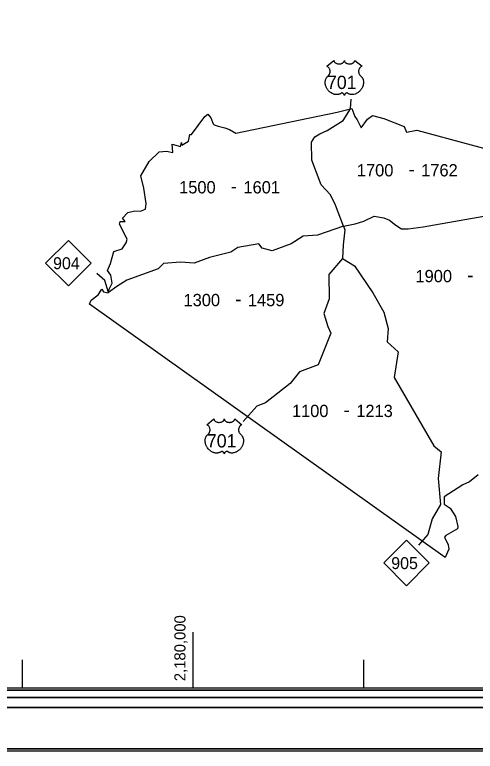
# Model space of a CAD drawing. Extents: x 5197761 to 5514561, y 1890130 to 2080942.
# Drawn here: x 5400329 to 5427322, y 1890130 to 1933323 of the extents above; entities that cross this region are included whole.
import ezdxf

# ---------------------------------------------------------------- set-up
doc = ezdxf.new("R2010")
doc.units = 0
for name, color, linetype in [('Exist Road Primary NC Shield CELL', 7, 'Continuous'), ('Exist Road Primary NC Shield Number Label', 7, 'Continuous'), ('Exist Road Primary US Shield CELL', 7, 'Continuous'), ('Exist Road Primary US Shield Number Label', 7, 'Continuous'), ('Map Preparation Base KeyMap Boundary Shape', 7, 'Continuous'), ('Map Preparation Base KeyMap Note Label', 7, 'Continuous'), ('Map Preparation Base StatePlane Tick Label', 7, 'Continuous'), ('Map Preparation Base StatePlane Tick Mark', 7, 'Continuous'), ('Map Preparation Border Antique Large Shape', 7, 'Continuous'), ('Map Preparation Border Antique Small Shape', 7, 'Continuous'), ('Map Preparation Border Black Inside Shape', 7, 'Continuous'), ('Map Preparation Border Black Middle Shape', 7, 'Continuous'), ('Map Preparation Border Black Outside Shape', 7, 'Continuous')]:
    doc.layers.add(name, color=color, linetype=linetype)

msp = doc.modelspace()

# ---------------------------------------------------------------- linework, layer by layer
at = {"layer": 'Exist Road Primary NC Shield CELL'}
for points in [[(5402139, 1918759), (5403471, 1920091), (5404803, 1918759), (5403471, 1917427)], [(5421960, 1901173), (5423292, 1902505), (5424624, 1901173), (5423292, 1899841)]]:
    msp.add_lwpolyline(points, close=True, dxfattribs=at)
at = {"layer": 'Exist Road Primary US Shield CELL'}
for points in [[(5419042, 1930642), (5419043, 1930625), (5419047, 1930604), (5419050, 1930593), (5419060, 1930572), (5419076, 1930548), (5419099, 1930524), (5419124, 1930503), (5419141, 1930492), (5419170, 1930477), (5419203, 1930463), (5419240, 1930452), (5419277, 1930445), (5419318, 1930440), (5419358, 1930440), (5419402, 1930443), (5419450, 1930452), (5419473, 1930458), (5419498, 1930466), (5419521, 1930476), (5419546, 1930490), (5419566, 1930503), (5419582, 1930514), (5419605, 1930536), (5419623, 1930558), (5419630, 1930571), (5419637, 1930583), (5419646, 1930608), (5419648, 1930620), (5419650, 1930643), (5419652, 1930623), (5419654, 1930611), (5419657, 1930599), (5419662, 1930586), (5419671, 1930568), (5419681, 1930553), (5419700, 1930531), (5419712, 1930520), (5419722, 1930511), (5419751, 1930491), (5419785, 1930474), (5419802, 1930467), (5419819, 1930461), (5419840, 1930454), (5419863, 1930449), (5419885, 1930445), (5419907, 1930442), (5419930, 1930440), (5419949, 1930440), (5419972, 1930440), (5419994, 1930441), (5420016, 1930444), (5420040, 1930448), (5420059, 1930452), (5420085, 1930459), (5420108, 1930467), (5420128, 1930476), (5420154, 1930490), (5420176, 1930503), (5420191, 1930515), (5420210, 1930533), (5420227, 1930553), (5420238, 1930568), (5420245, 1930583), (5420252, 1930599), (5420256, 1930616), (5420258, 1930631), (5420258, 1930644), (5420684, 1930305), (5420673, 1930301), (5420650, 1930290), (5420632, 1930279), (5420603, 1930258), (5420590, 1930247), (5420578, 1930235), (5420566, 1930223), (5420556, 1930211), (5420544, 1930194), (5420533, 1930177), (5420522, 1930158), (5420514, 1930142), (5420501, 1930107), (5420495, 1930086), (5420491, 1930068), (5420486, 1930030), (5420484, 1930012), (5420484, 1929994), (5420485, 1929975), (5420487, 1929957), (5420490, 1929938), (5420493, 1929921), (5420499, 1929901), (5420506, 1929877), (5420515, 1929855), (5420535, 1929818), (5420560, 1929780), (5420578, 1929759), (5420595, 1929741), (5420622, 1929719), (5420636, 1929706), (5420652, 1929690), (5420679, 1929659), (5420689, 1929644), (5420700, 1929628), (5420710, 1929611), (5420720, 1929593), (5420728, 1929577), (5420743, 1929541), (5420754, 1929505), (5420759, 1929487), (5420767, 1929445), (5420770, 1929424), (5420774, 1929384), (5420774, 1929335), (5420770, 1929288), (5420761, 1929233), (5420754, 1929201), (5420743, 1929163), (5420732, 1929130), (5420712, 1929081), (5420695, 1929046), (5420673, 1929005), (5420658, 1928980), (5420640, 1928953), (5420617, 1928923), (5420591, 1928890), (5420560, 1928856), (5420535, 1928830), (5420501, 1928801), (5420481, 1928784), (5420453, 1928763), (5420414, 1928736), (5420375, 1928714), (5420342, 1928697), (5420313, 1928685), (5420275, 1928670), (5420212, 1928653), (5420190, 1928648), (5420162, 1928644), (5420137, 1928642), (5420113, 1928640), (5420079, 1928640), (5420046, 1928643), (5420015, 1928647), (5419983, 1928654), (5419949, 1928664), (5419918, 1928676), (5419887, 1928692), (5419835, 1928725), (5419819, 1928733), (5419811, 1928735), (5419791, 1928736), (5419771, 1928732), (5419752, 1928724), (5419740, 1928718), (5419724, 1928708), (5419712, 1928698), (5419698, 1928684), (5419688, 1928673), (5419680, 1928664), (5419665, 1928640), (5419660, 1928629), (5419654, 1928615), (5419650, 1928594), (5419643, 1928620), (5419635, 1928638), (5419626, 1928653), (5419617, 1928666), (5419602, 1928683), (5419589, 1928696), (5419572, 1928709), (5419555, 1928720), (5419542, 1928727), (5419529, 1928731), (5419514, 1928735), (5419501, 1928736), (5419491, 1928736), (5419477, 1928733), (5419458, 1928719), (5419439, 1928706), (5419420, 1928694), (5419396, 1928681), (5419379, 1928673), (5419358, 1928665), (5419334, 1928657), (5419308, 1928651), (5419281, 1928645), (5419257, 1928642), (5419232, 1928639), (5419209, 1928638), (5419185, 1928639), (5419163, 1928641), (5419137, 1928643), (5419105, 1928648), (5419078, 1928654), (5419050, 1928661), (5419021, 1928670), (5418990, 1928682), (5418952, 1928699), (5418925, 1928713), (5418883, 1928737), (5418833, 1928771), (5418795, 1928802), (5418768, 1928827), (5418727, 1928868), (5418704, 1928895), (5418666, 1928943), (5418643, 1928978), (5418627, 1929003), (5418604, 1929045), (5418592, 1929071), (5418576, 1929108), (5418563, 1929143), (5418553, 1929175), (5418547, 1929196), (5418539, 1929233), (5418534, 1929258), (5418529, 1929294), (5418527, 1929331), (5418526, 1929366), (5418527, 1929394), (5418530, 1929428), (5418536, 1929463), (5418543, 1929494), (5418549, 1929515), (5418558, 1929542), (5418570, 1929571), (5418584, 1929600), (5418597, 1929623), (5418614, 1929648), (5418631, 1929669), (5418653, 1929693), (5418675, 1929715), (5418696, 1929731), (5418720, 1929756), (5418733, 1929770), (5418749, 1929790), (5418761, 1929809), (5418771, 1929826), (5418784, 1929851), (5418792, 1929870), (5418801, 1929898), (5418806, 1929918), (5418811, 1929944), (5418815, 1929969), (5418816, 1929999), (5418815, 1930024), (5418812, 1930053), (5418806, 1930082), (5418800, 1930106), (5418789, 1930134), (5418779, 1930155), (5418763, 1930183), (5418745, 1930209), (5418726, 1930230), (5418707, 1930249), (5418689, 1930263), (5418672, 1930275), (5418651, 1930288), (5418630, 1930298), (5418617, 1930304)], [(5412004, 1909621), (5412005, 1909603), (5412009, 1909582), (5412012, 1909571), (5412022, 1909551), (5412038, 1909526), (5412061, 1909503), (5412086, 1909482), (5412103, 1909471), (5412132, 1909455), (5412165, 1909441), (5412202, 1909431), (5412239, 1909423), (5412280, 1909419), (5412320, 1909418), (5412364, 1909421), (5412412, 1909431), (5412435, 1909436), (5412460, 1909445), (5412483, 1909454), (5412508, 1909468), (5412528, 1909481), (5412544, 1909493), (5412567, 1909514), (5412585, 1909537), (5412592, 1909549), (5412599, 1909561), (5412608, 1909587), (5412610, 1909598), (5412612, 1909622), (5412614, 1909602), (5412616, 1909590), (5412619, 1909577), (5412624, 1909565), (5412633, 1909547), (5412643, 1909531), (5412662, 1909509), (5412674, 1909498), (5412684, 1909489), (5412713, 1909469), (5412747, 1909452), (5412764, 1909445), (5412781, 1909439), (5412802, 1909433), (5412825, 1909427), (5412847, 1909423), (5412869, 1909420), (5412892, 1909418), (5412911, 1909418), (5412934, 1909418), (5412956, 1909419), (5412978, 1909422), (5413002, 1909426), (5413021, 1909430), (5413047, 1909437), (5413070, 1909445), (5413090, 1909454), (5413116, 1909468), (5413138, 1909481), (5413153, 1909494), (5413172, 1909511), (5413189, 1909531), (5413200, 1909546), (5413207, 1909561), (5413214, 1909577), (5413218, 1909595), (5413220, 1909609), (5413220, 1909622), (5413646, 1909283), (5413636, 1909280), (5413612, 1909268), (5413594, 1909257), (5413565, 1909237), (5413552, 1909226), (5413540, 1909214), (5413528, 1909201), (5413518, 1909189), (5413506, 1909172), (5413495, 1909155), (5413484, 1909136), (5413476, 1909120), (5413463, 1909086), (5413457, 1909064), (5413453, 1909046), (5413448, 1909008), (5413446, 1908990), (5413446, 1908972), (5413447, 1908953), (5413449, 1908935), (5413452, 1908916), (5413455, 1908900), (5413461, 1908879), (5413468, 1908856), (5413477, 1908833), (5413497, 1908796), (5413522, 1908758), (5413540, 1908737), (5413557, 1908719), (5413584, 1908697), (5413598, 1908684), (5413614, 1908668), (5413641, 1908637), (5413651, 1908623), (5413662, 1908606), (5413672, 1908590), (5413682, 1908571), (5413690, 1908556), (5413705, 1908519), (5413716, 1908484), (5413721, 1908465), (5413729, 1908423), (5413732, 1908403), (5413736, 1908362), (5413736, 1908313), (5413732, 1908266), (5413723, 1908212), (5413716, 1908179), (5413705, 1908141), (5413694, 1908108), (5413674, 1908060), (5413657, 1908025), (5413635, 1907983), (5413620, 1907958), (5413602, 1907932), (5413579, 1907901), (5413553, 1907869), (5413522, 1907834), (5413497, 1907809), (5413463, 1907779), (5413443, 1907763), (5413415, 1907741), (5413376, 1907715), (5413337, 1907692), (5413304, 1907676), (5413275, 1907663), (5413237, 1907649), (5413174, 1907631), (5413152, 1907627), (5413124, 1907623), (5413099, 1907620), (5413075, 1907619), (5413041, 1907619), (5413008, 1907621), (5412977, 1907626), (5412945, 1907632), (5412911, 1907642), (5412880, 1907655), (5412849, 1907670), (5412797, 1907703), (5412781, 1907711), (5412773, 1907713), (5412753, 1907714), (5412733, 1907710), (5412714, 1907703), (5412702, 1907696), (5412686, 1907686), (5412674, 1907676), (5412660, 1907663), (5412650, 1907651), (5412642, 1907642), (5412627, 1907619), (5412622, 1907608), (5412616, 1907593), (5412612, 1907572), (5412605, 1907599), (5412597, 1907616), (5412588, 1907631), (5412579, 1907645), (5412564, 1907662), (5412551, 1907675), (5412534, 1907688), (5412517, 1907698), (5412504, 1907705), (5412491, 1907710), (5412476, 1907714), (5412463, 1907715), (5412453, 1907714), (5412439, 1907711), (5412420, 1907697), (5412401, 1907685), (5412382, 1907672), (5412358, 1907660), (5412341, 1907652), (5412320, 1907644), (5412296, 1907636), (5412270, 1907629), (5412243, 1907624), (5412219, 1907620), (5412194, 1907618), (5412171, 1907617), (5412147, 1907617), (5412125, 1907619), (5412099, 1907621), (5412067, 1907626), (5412040, 1907632), (5412012, 1907639), (5411983, 1907649), (5411952, 1907660), (5411914, 1907677), (5411887, 1907691), (5411845, 1907715), (5411795, 1907750), (5411757, 1907780), (5411730, 1907805), (5411689, 1907846), (5411666, 1907873), (5411628, 1907921), (5411605, 1907956), (5411589, 1907982), (5411566, 1908023), (5411554, 1908049), (5411538, 1908087), (5411525, 1908121), (5411515, 1908154), (5411509, 1908175), (5411501, 1908211), (5411496, 1908237), (5411491, 1908272), (5411489, 1908310), (5411488, 1908344), (5411489, 1908373), (5411492, 1908406), (5411498, 1908442), (5411505, 1908472), (5411511, 1908494), (5411520, 1908520), (5411532, 1908550), (5411546, 1908578), (5411559, 1908601), (5411576, 1908626), (5411593, 1908648), (5411615, 1908671), (5411637, 1908693), (5411658, 1908710), (5411682, 1908734), (5411695, 1908749), (5411711, 1908769), (5411723, 1908788), (5411733, 1908805), (5411746, 1908829), (5411754, 1908848), (5411763, 1908877), (5411768, 1908897), (5411773, 1908923), (5411777, 1908947), (5411778, 1908977), (5411777, 1909002), (5411774, 1909032), (5411768, 1909060), (5411762, 1909085), (5411751, 1909113), (5411741, 1909133), (5411725, 1909161), (5411707, 1909187), (5411688, 1909208), (5411669, 1909227), (5411651, 1909241), (5411634, 1909253), (5411613, 1909266), (5411592, 1909277), (5411579, 1909282)]]:
    msp.add_lwpolyline(points, close=True, dxfattribs=at)
at = {"layer": 'Map Preparation Base KeyMap Boundary Shape'}
for points in [[(5419606, 1920931), (5419136, 1922152), (5418831, 1922764), (5418290, 1923353), (5417748, 1924788), (5417725, 1925848), (5417913, 1926154), (5418219, 1926342), (5418642, 1926530), (5419583, 1927119), (5420007, 1927801), (5420054, 1928366)], [(5404712, 1916341), (5404815, 1916576), (5405212, 1916906), (5405440, 1917228), (5405541, 1917067), (5405809, 1917013), (5405870, 1917221), (5406037, 1917577), (5405957, 1918054), (5405776, 1918316), (5405943, 1918732), (5406131, 1919444), (5406628, 1919598), (5406856, 1919940), (5406910, 1920162), (5406460, 1921042), (5406514, 1921196), (5406796, 1921203), (5406655, 1921391), (5406950, 1921720), (5407359, 1921814), (5407702, 1921807), (5407997, 1921921), (5408030, 1922250), (5407903, 1923150), (5407729, 1923882), (5408218, 1924714), (5408802, 1925278), (5409218, 1925319), (5409601, 1925245), (5409554, 1925742), (5410050, 1925594), (5410111, 1925836), (5410118, 1925674), (5410520, 1925909), (5410587, 1926306), (5410688, 1926292), (5411480, 1927353), (5411641, 1927487), (5411829, 1927279), (5411963, 1926923), (5412023, 1926876), (5412258, 1926782), (5412641, 1926695), (5412916, 1926594), (5413285, 1926373), (5419231, 1927608), (5420090, 1927823), (5420264, 1927353), (5420398, 1927152), (5420627, 1926682), (5421002, 1927192), (5421298, 1927420), (5421969, 1927246), (5423163, 1926762), (5423298, 1926440), (5423902, 1926547), (5430263, 1924842)], [(5419606, 1920931), (5420289, 1921069), (5420783, 1921211), (5421395, 1921517), (5421960, 1921422), (5422289, 1921281), (5422665, 1920975), (5422995, 1920763), (5423395, 1920763), (5424265, 1920881), (5428147, 1921564), (5428782, 1921728), (5429841, 1921893), (5432488, 1922331)], [(5419603, 1920920), (5418071, 1920395), (5417229, 1920344), (5416540, 1919884), (5415418, 1919476), (5414831, 1919629), (5414627, 1919884), (5413403, 1919680), (5412995, 1919400), (5411745, 1919093), (5410853, 1918762), (5410037, 1918813), (5409042, 1918736), (5408736, 1918430), (5406899, 1917766), (5406313, 1917384), (5405824, 1917043), (5405609, 1917735), (5405132, 1918150)], [(5419603, 1920920), (5419686, 1920713), (5419575, 1919822), (5419534, 1919028)], [(5419534, 1919028), (5418734, 1918098), (5418759, 1916669), (5418453, 1915801), (5418683, 1915036), (5418861, 1914653), (5418122, 1912790), (5417025, 1912382), (5416464, 1911693), (5415035, 1910570), (5414525, 1910366), (5413709, 1909473)], [(5419534, 1919028), (5420238, 1918593), (5421312, 1917020), (5421970, 1915884), (5422209, 1914926), (5422149, 1914148), (5422807, 1913550), (5422568, 1912054), (5424900, 1908046), (5425318, 1907687), (5425139, 1906131), (5425286, 1904606), (5424789, 1903753), (5424548, 1902844), (5423994, 1902219)], [(5427485, 1906337), (5426975, 1905934), (5426599, 1905746), (5425499, 1905048), (5425499, 1904618), (5425848, 1904377), (5426170, 1903893), (5426304, 1903302), (5426277, 1903168), (5425606, 1902792), (5425526, 1902685), (5425740, 1902228), (5425781, 1901988), (5425553, 1901493), (5404712, 1916341)]]:
    msp.add_lwpolyline(points, dxfattribs=at)
at = {"layer": 'Map Preparation Base StatePlane Tick Mark'}
for p, q in [((5410787, 1893858), (5410787, 1897109)), ((5400787, 1893858), (5400787, 1895484)), ((5420787, 1893858), (5420787, 1895484))]:
    msp.add_line(p, q, dxfattribs=at)
at = {"layer": 'Map Preparation Border Antique Large Shape'}
msp.add_lwpolyline([(5197907, 2074783), (5207205, 2074783), (5207205, 1892697), (5512539, 1892697), (5512539, 2072359), (5207205, 2072359), (5207205, 2074783), (5514414, 2074783), (5514414, 1890276), (5197907, 1890276)], close=True, dxfattribs=at)
at = {"layer": 'Map Preparation Border Antique Small Shape'}
msp.add_lwpolyline([(5207791, 2071720), (5208220, 2071720), (5208220, 1893712), (5511524, 1893712), (5511524, 2071291), (5208220, 2071291), (5208220, 2071720), (5207791, 2071720), (5511953, 2071720), (5511953, 1893283), (5208220, 1893283), (5207791, 1893283)], close=True, dxfattribs=at)
at = {"layer": 'Map Preparation Border Black Inside Shape'}
msp.add_lwpolyline([(5208220, 2071291), (5511524, 2071291), (5511524, 1893712), (5208366, 1893712), (5208366, 1893858), (5511378, 1893858), (5511378, 2071145), (5208366, 2071145), (5208366, 1893858), (5208366, 1893712), (5208220, 1893712), (5208220, 1893858)], close=True, dxfattribs=at)
at = {"layer": 'Map Preparation Border Black Middle Shape'}
msp.add_lwpolyline([(5207205, 2072359), (5512539, 2072359), (5512539, 1892697), (5511953, 1892697), (5207791, 1892697), (5207791, 1893283), (5511953, 1893283), (5511953, 2071720), (5207791, 2071720), (5207791, 1892697), (5207205, 1892697)], close=True, dxfattribs=at)
at = {"layer": 'Map Preparation Border Black Outside Shape'}
msp.add_lwpolyline([(5197761, 2074930), (5514561, 2074930), (5514561, 1890130), (5197907, 1890130), (5197907, 1890276), (5514414, 1890276), (5514414, 2074783), (5197907, 2074783), (5197907, 1890130), (5197761, 1890130)], close=True, dxfattribs=at)

# ---------------------------------------------------------------- texts
at = {"layer": 'Exist Road Primary NC Shield Number Label'}
for s, p in [('904', (5402576, 1918400)), ('905', (5422397, 1900814))]:
    msp.add_text(s, height=700, dxfattribs=at).set_placement(p)
at = {"layer": 'Exist Road Primary US Shield Number Label'}
for p in [(5418626, 1928967), (5411588, 1907946)]:
    msp.add_text('701', height=780, dxfattribs=at).set_placement(p)
at = {"layer": 'Map Preparation Base KeyMap Note Label'}
for s, height, p in [('1700', 720, (5420382, 1923843)), ('1762', 720, (5424152, 1923843)), ('-', 820, (5423408, 1923860)), ('1500', 720, (5409963, 1922845)), ('1601', 720, (5413734, 1922845)), ('-', 820, (5412989, 1922863)), ('1900', 720, (5423818, 1917636)), ('-', 820, (5426844, 1917654)), ('1300', 720, (5410222, 1916232)), ('1459', 720, (5413993, 1916232)), ('-', 820, (5413248, 1916250)), ('1100', 720, (5416576, 1909730)), ('1213', 720, (5420347, 1909730)), ('-', 820, (5419603, 1909748))]:
    msp.add_text(s, height=height, dxfattribs=at).set_placement(p)
at = {"layer": 'Map Preparation Base StatePlane Tick Label'}
msp.add_text('2,180,000', height=650, rotation=90, dxfattribs=at).set_placement((5410335, 1894241))

doc.saveas('drawing.dxf')
